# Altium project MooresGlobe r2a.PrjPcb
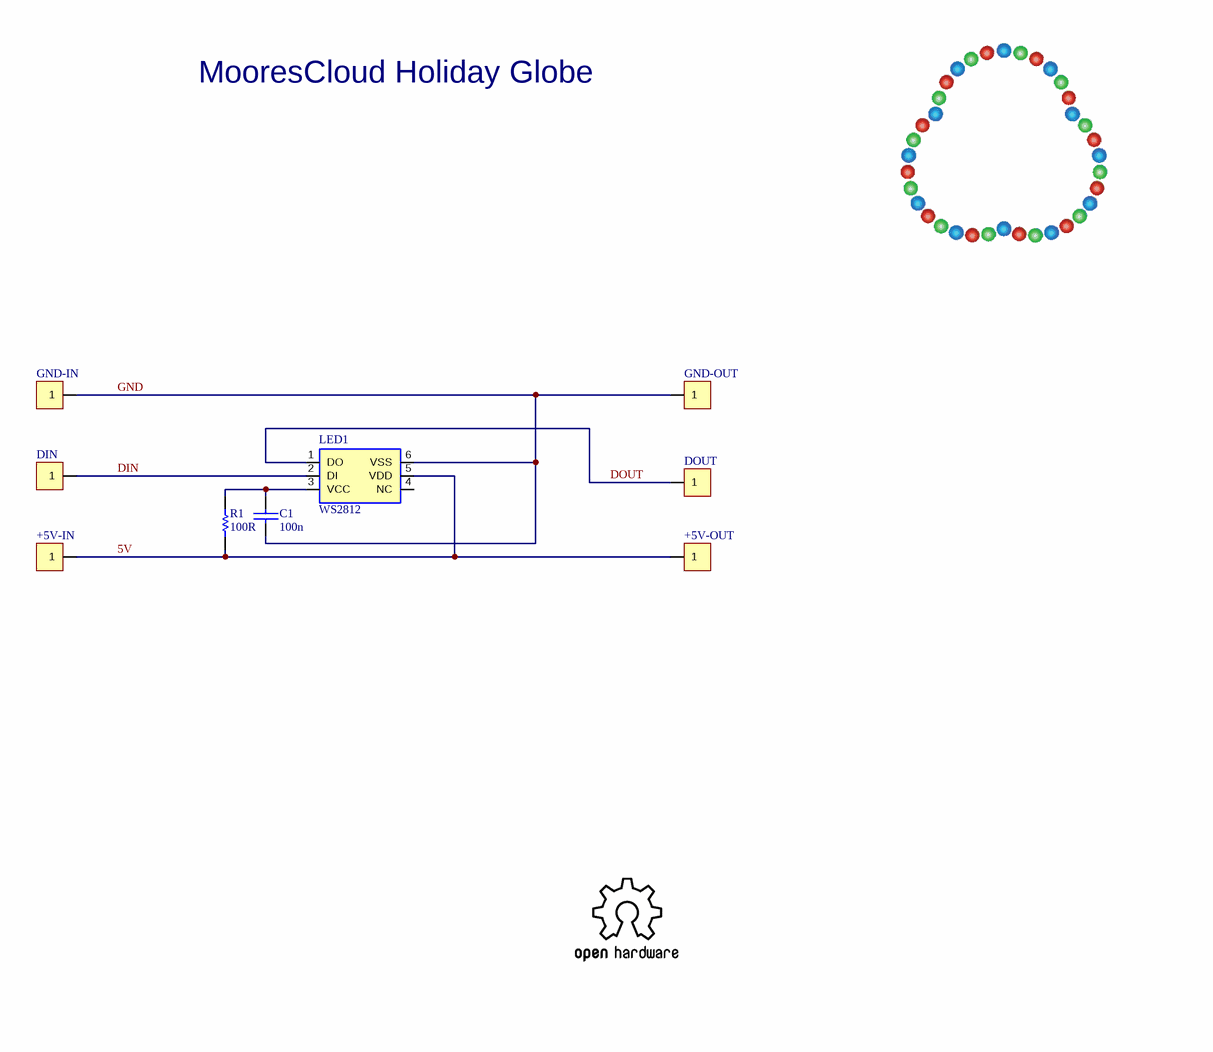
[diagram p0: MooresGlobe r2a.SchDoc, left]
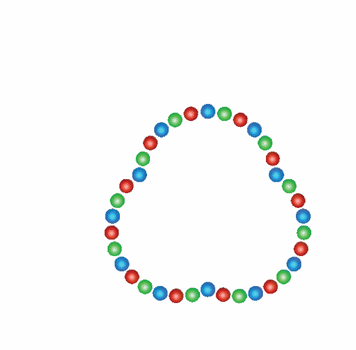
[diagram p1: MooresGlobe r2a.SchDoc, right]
1 sheet, 9 parts. Net scope: global (net labels, ports and power ports of the same name join across sheets).
Board files: MooresGlobe r2a.PcbDoc, MooresGlobe r2a Panel 10x10.PcbDoc, MooresGlobe r2a Panel 10x10 (no embed).PcbDoc

## Sheet MooresGlobe r2a.SchDoc: MooresGlobe for Holiday
size A4; DrawnBy: KJM; Organization: MooresCloud; Revision: 2; SheetNumber: 1; SheetTotal: 1

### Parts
+5V-IN  +5V  [Solder Pad]  (value not drawn)  (no BOM)
+5V-OUT  +5V  [Solder Pad]  (value not drawn)  (no BOM)
C1  100n  [ARA_0603]
DIN  DIN  [Solder Pad]  (value not drawn)  (no BOM)
DOUT  DOUT  [Solder Pad]  (value not drawn)  (no BOM)
GND-IN  GND  [Solder Pad]  (value not drawn)  (no BOM)
GND-OUT  GND  [Solder Pad]  (value not drawn)  (no BOM)
LED1  WS2812  [PLCC6-IPC]
R1  100R  [ARA_0603]

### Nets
5V: +5V-IN.1 +5V-OUT.1 LED1.5(VDD) R1.1
DIN: DIN.1 LED1.2(DI)
DOUT: DOUT.1 LED1.1(DO)
GND: C1.2 GND-IN.1 GND-OUT.1 LED1.6(VSS)
NetC1_1: C1.1 LED1.3(VCC) R1.2

Not connected (* = marked no-connect by the designer): LED1 4(NC)

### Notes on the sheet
- MooresCloud Holiday Globe

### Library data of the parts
+5V-IN +5V-OUT DIN DOUT GND-IN GND-OUT = Solder Pad
C1 = CAP: Capacitor Ceramic 100n 50V Y5V 0603; 1.Manufacturer: Yageo; 4.CatNo: 311-1343-2-ND; 2.MfgNo: CC0603ZRY5V9BB104; 9.UnitCost: 0.00206
LED1 = WS2812: WorldSemi WS2812 Smart RGB LED; 4.CatNo: sc-WS2811-5050; 9.UnitCost: 0.15
R1 = Res Semi: Resistor 100R 0.1W 5% 0603; 1.Manufacturer: Yageo; 4.CatNo: 311-100GRTR-ND; 2.MfgNo: RC0603JR-07100RL; 9.UnitCost: 0.00092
